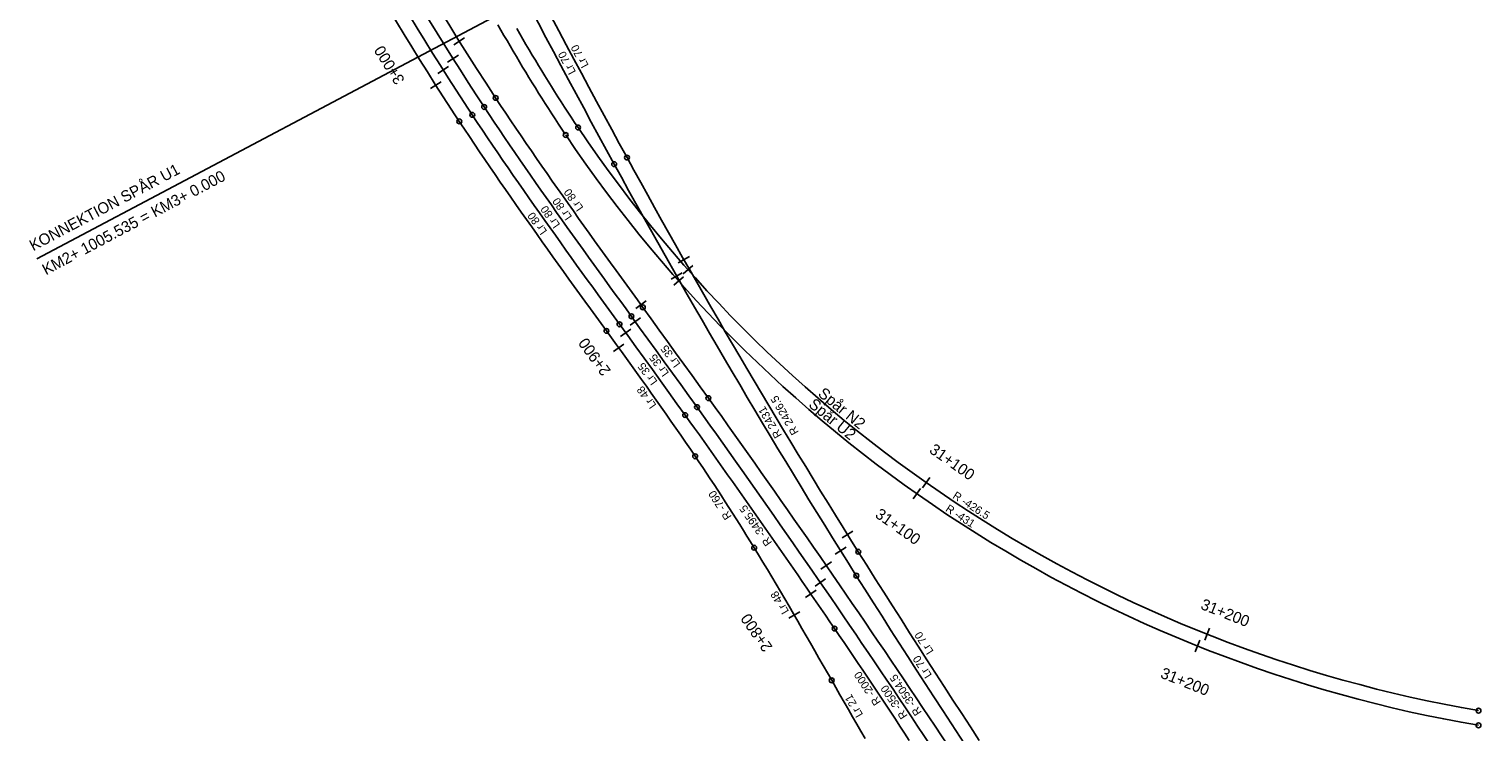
# Model space of a CAD drawing. Extents: x 149855 to 151460, y 6580726 to 6583068.
# Drawn here: x 150980.3 to 151434, y 6581086.8 to 6581306.4 of the extents above; entities that cross this region are included whole.
import ezdxf

# ---------------------------------------------------------------- set-up
doc = ezdxf.new("R2010")
doc.units = 0
for name, color, linetype in [('Hektometer L', 7, 'Continuous'), ('Hektometer T', 7, 'Continuous'), ('Kilometer spm P', 7, 'Continuous'), ('Kilometer spm T', 7, 'Continuous'), ('Konnektion längdmätning L', 7, 'Continuous'), ('Konnektion längdmätning T', 7, 'Continuous'), ('Spår nr T', 7, 'Continuous'), ('Spårgeometri T', 7, 'Continuous'), ('Spårmitt L', 7, 'Continuous'), ('Tp bef behålls P', 7, 'Continuous')]:
    doc.layers.add(name, color=color, linetype=linetype)

msp = doc.modelspace()

# ---------------------------------------------------------------- linework, layer by layer
at = {"layer": 'Hektometer L'}
for points in [[(151113.01, 6581301.55), (151116.4, 6581303.68)], [(151111.05, 6581296.14), (151114.43, 6581298.28)], [(151108.01, 6581292.57), (151111.39, 6581294.72)], [(151105.69, 6581287.83), (151109.07, 6581289.98)], [(151183.16, 6581233.42), (151186.64, 6581235.4)], [(151180.9, 6581228.3), (151184.37, 6581230.28)], [(151169.84, 6581219.13), (151173.08, 6581221.48)], [(151168.07, 6581213.86), (151171.31, 6581216.2)], [(151165.1, 6581210.34), (151168.34, 6581212.69)], [(151162.88, 6581205.67), (151166.12, 6581208.02)], [(151261.74, 6581166.35), (151259.45, 6581163.08)], [(151258.85, 6581162.86), (151256.55, 6581159.59)], [(151234.33, 6581147.42), (151237.73, 6581149.54)], [(151232.19, 6581142.37), (151235.58, 6581144.49)], [(151227.73, 6581137.65), (151231.03, 6581139.93)], [(151225.91, 6581132.34), (151229.2, 6581134.61)], [(151222.9, 6581128.81), (151226.2, 6581131.07)], [(151217.65, 6581122.31), (151221.11, 6581124.32)], [(151346.14, 6581115.5), (151344.65, 6581111.79)], [(151349.13, 6581119.18), (151347.65, 6581115.46)]]:
    msp.add_lwpolyline(points, dxfattribs=at)
at = {"layer": 'Kilometer spm P'}
for p, q in [((151184.79, 6581229.03), (151181.79, 6581226.38)), ((151187.72, 6581232.54), (151184.71, 6581229.9))]:
    msp.add_line(p, q, dxfattribs=at)
at = {"layer": 'Konnektion längdmätning L'}
msp.add_line((150982.75, 6581234.65), (151228.43, 6581364.77), dxfattribs=at)
at = {"layer": 'Spårmitt L'}
for points in [[(151163.13, 6581264.21), (151160.73, 6581268.6), (151158.35, 6581272.99), (151155.96, 6581277.39), (151153.59, 6581281.79), (151151.22, 6581286.19), (151148.86, 6581290.6), (151146.5, 6581295.01), (151144.15, 6581299.42), (151141.8, 6581303.84), (151139.46, 6581308.25), (151137.12, 6581312.67), (151134.78, 6581317.09), (151132.44, 6581321.51), (151130.1, 6581325.93)], [(151167.13, 6581266.28), (151164.73, 6581270.66), (151162.34, 6581275.06), (151159.96, 6581279.45), (151157.59, 6581283.85), (151155.22, 6581288.26), (151152.86, 6581292.66), (151150.5, 6581297.07), (151148.15, 6581301.48), (151145.8, 6581305.9), (151143.45, 6581310.31), (151141.11, 6581314.73), (151138.77, 6581319.15), (151136.43, 6581323.57), (151134.09, 6581327.99)], [(151126.77, 6581307.79), (151127.72, 6581306.13), (151128.68, 6581304.47), (151129.64, 6581302.81), (151130.6, 6581301.16), (151131.57, 6581299.51), (151132.55, 6581297.86), (151133.53, 6581296.21), (151134.51, 6581294.57), (151135.5, 6581292.93), (151136.5, 6581291.3), (151137.5, 6581289.66), (151138.51, 6581288.03), (151139.52, 6581286.41), (151140.54, 6581284.79), (151141.56, 6581283.17), (151142.59, 6581281.56), (151143.63, 6581279.95), (151144.68, 6581278.34), (151145.73, 6581276.74), (151146.78, 6581275.14), (151147.85, 6581273.55)], [(151132.66, 6581306.58), (151133.62, 6581304.92), (151134.59, 6581303.27), (151135.56, 6581301.62), (151136.53, 6581299.97), (151137.51, 6581298.32), (151138.5, 6581296.68), (151139.49, 6581295.04), (151140.48, 6581293.41), (151141.48, 6581291.77), (151142.49, 6581290.15), (151143.5, 6581288.52), (151144.52, 6581286.9), (151145.55, 6581285.28), (151146.58, 6581283.67), (151147.62, 6581282.06), (151148.66, 6581280.46), (151149.71, 6581278.86), (151150.77, 6581277.26), (151151.84, 6581275.67)], [(151172.07, 6581219.47), (151170.39, 6581221.79), (151168.71, 6581224.1), (151167.04, 6581226.41), (151165.36, 6581228.73), (151163.69, 6581231.04), (151162.01, 6581233.36), (151160.34, 6581235.68), (151158.67, 6581237.99), (151157, 6581240.31), (151155.34, 6581242.64), (151153.68, 6581244.96), (151152.02, 6581247.28), (151150.36, 6581249.61), (151148.71, 6581251.94), (151147.06, 6581254.28), (151145.41, 6581256.61), (151143.77, 6581258.95), (151142.13, 6581261.29), (151140.5, 6581263.64), (151138.88, 6581265.99), (151137.25, 6581268.34), (151135.64, 6581270.69), (151134.03, 6581273.06), (151132.42, 6581275.42), (151130.83, 6581277.79), (151129.24, 6581280.16), (151127.65, 6581282.54), (151126.08, 6581284.92)], [(151164.79, 6581214.18), (151163.11, 6581216.49), (151161.43, 6581218.81), (151159.76, 6581221.12), (151158.08, 6581223.43), (151156.41, 6581225.75), (151154.73, 6581228.07), (151153.06, 6581230.38), (151151.39, 6581232.7), (151149.72, 6581235.02), (151148.06, 6581237.34), (151146.4, 6581239.67), (151144.74, 6581241.99), (151143.08, 6581244.32), (151141.42, 6581246.65), (151139.77, 6581248.98), (151138.13, 6581251.32), (151136.49, 6581253.65), (151134.85, 6581256), (151133.22, 6581258.34), (151131.59, 6581260.69), (151129.97, 6581263.04), (151128.35, 6581265.4), (151126.74, 6581267.76), (151125.13, 6581270.12), (151123.53, 6581272.49), (151121.94, 6581274.86), (151120.36, 6581277.24), (151118.78, 6581279.62)], [(151168.51, 6581216.66), (151166.83, 6581218.97), (151165.15, 6581221.29), (151163.48, 6581223.6), (151161.8, 6581225.91), (151160.13, 6581228.23), (151158.45, 6581230.54), (151156.78, 6581232.86), (151155.11, 6581235.18), (151153.44, 6581237.5), (151151.78, 6581239.82), (151150.11, 6581242.14), (151148.45, 6581244.47), (151146.8, 6581246.8), (151145.14, 6581249.13), (151143.49, 6581251.46), (151141.85, 6581253.79), (151140.21, 6581256.13), (151138.57, 6581258.47), (151136.94, 6581260.82), (151135.31, 6581263.17), (151133.69, 6581265.52), (151132.07, 6581267.88), (151130.46, 6581270.23), (151128.85, 6581272.6), (151127.26, 6581274.97), (151125.66, 6581277.34), (151124.08, 6581279.72), (151122.5, 6581282.1)], [(151160.69, 6581212.11), (151159.02, 6581214.42), (151157.34, 6581216.74), (151155.67, 6581219.05), (151153.99, 6581221.37), (151152.32, 6581223.68), (151150.65, 6581226), (151148.98, 6581228.32), (151147.31, 6581230.64), (151145.65, 6581232.96), (151143.98, 6581235.28), (151142.32, 6581237.61), (151140.66, 6581239.93), (151139.01, 6581242.26), (151137.36, 6581244.59), (151135.71, 6581246.93), (151134.06, 6581249.26), (151132.42, 6581251.6), (151130.79, 6581253.95), (151129.16, 6581256.29), (151127.53, 6581258.64), (151125.91, 6581260.99), (151124.29, 6581263.35), (151122.68, 6581265.71), (151121.08, 6581268.08), (151119.48, 6581270.44), (151117.89, 6581272.82), (151116.31, 6581275.2), (151114.73, 6581277.58)], [(151192.56, 6581191.1), (151190.01, 6581194.66), (151187.46, 6581198.21), (151184.9, 6581201.75), (151182.33, 6581205.3), (151179.77, 6581208.85), (151177.2, 6581212.39), (151174.63, 6581215.93), (151172.07, 6581219.47)], [(151189.01, 6581188.29), (151186.45, 6581191.84), (151183.9, 6581195.39), (151181.34, 6581198.94), (151178.78, 6581202.49), (151176.21, 6581206.03), (151173.64, 6581209.58), (151171.08, 6581213.12), (151168.51, 6581216.66)], [(151188.43, 6581172.93), (151186.93, 6581175.14), (151185.42, 6581177.34), (151183.91, 6581179.54), (151182.39, 6581181.73), (151180.87, 6581183.92), (151179.34, 6581186.1), (151177.8, 6581188.28), (151176.26, 6581190.46), (151174.72, 6581192.63), (151173.17, 6581194.8), (151171.62, 6581196.97), (151170.06, 6581199.14), (151168.5, 6581201.3), (151166.94, 6581203.46), (151165.38, 6581205.63), (151163.82, 6581207.79), (151162.26, 6581209.95), (151160.69, 6581212.11)], [(151185.29, 6581185.81), (151182.73, 6581189.36), (151180.18, 6581192.91), (151177.62, 6581196.46), (151175.05, 6581200.01), (151172.49, 6581203.55), (151169.92, 6581207.1), (151167.36, 6581210.64), (151164.79, 6581214.18)], [(151231.08, 6581102.93), (151229.76, 6581105.25), (151228.43, 6581107.56), (151227.11, 6581109.88), (151225.79, 6581112.19), (151224.46, 6581114.51), (151223.13, 6581116.82), (151221.8, 6581119.13), (151220.46, 6581121.44), (151219.13, 6581123.74), (151217.78, 6581126.05), (151216.44, 6581128.35), (151215.08, 6581130.65), (151213.73, 6581132.94), (151212.36, 6581135.24), (151211, 6581137.52), (151209.62, 6581139.81), (151208.24, 6581142.09), (151206.85, 6581144.36)], [(151277.13, 6581084.17), (151274.42, 6581088.37), (151271.7, 6581092.57), (151268.99, 6581096.77), (151266.27, 6581100.97), (151263.56, 6581105.17), (151260.86, 6581109.37), (151258.15, 6581113.58), (151255.45, 6581117.79), (151252.76, 6581122), (151250.07, 6581126.21), (151247.39, 6581130.43), (151244.71, 6581134.66), (151242.04, 6581138.89), (151239.38, 6581143.12)], [(151276.68, 6581076.77), (151273.95, 6581080.96), (151271.22, 6581085.15), (151268.5, 6581089.34), (151265.77, 6581093.54), (151263.05, 6581097.73), (151260.34, 6581101.93), (151257.62, 6581106.13), (151254.91, 6581110.33), (151252.21, 6581114.54), (151249.51, 6581118.74), (151246.82, 6581122.96), (151244.13, 6581127.17), (151241.45, 6581131.4), (151238.78, 6581135.62)], [(151241.52, 6581084.71), (151240.21, 6581086.99), (151238.9, 6581089.26), (151237.59, 6581091.54), (151236.29, 6581093.82), (151234.98, 6581096.09), (151233.68, 6581098.37), (151232.38, 6581100.65), (151231.08, 6581102.93)]]:
    msp.add_lwpolyline(points, dxfattribs=at)
for centre, radius, start, end in [((151877.46, 6581780.33), 900, 202.28355, 213.39793), ((151881.9, 6581783.56), 919, 204.22992, 213.40688), ((151881.9, 6581783.56), 914.5, 204.24219, 213.43976), ((151881.95, 6581783.43), 910, 204.25457, 213.42998), ((151505.71, 6581513.74), 426.5, 213.9318, 260.2137), ((151505.71, 6581513.72), 431, 213.899, 260.3151), ((153295.26, 6582432.02), 2426.5, 208.71299, 212.08503), ((153295.27, 6582432), 2431, 208.70984, 212.22665), ((148345.36, 6579147.78), 3500, 32.03381, 35.662), ((148345.13, 6579148.16), 3504.5, 31.93168, 35.65829), ((148345.19, 6579148.07), 3495.5, 34.32399, 35.65902), ((150559.04, 6580746.94), 760, 31.52858, 34.09137), ((149580.27, 6579991.34), 2000, 33.12146, 34.32399)]:
    msp.add_arc(centre, radius, start, end, dxfattribs=at)
at = {"layer": 'Tp bef behålls P'}
for centre in [(151126.08, 6581284.92), (151118.78, 6581279.62), (151122.5, 6581282.1), (151114.73, 6581277.58), (151147.97, 6581273.34), (151151.84, 6581275.67), (151163.13, 6581264.21), (151167.13, 6581266.27), (151172.07, 6581219.47), (151164.79, 6581214.18), (151168.51, 6581216.66), (151160.69, 6581212.11), (151189.01, 6581188.29), (151192.56, 6581191.1), (151185.29, 6581185.81), (151188.43, 6581172.93), (151206.85, 6581144.36), (151239.39, 6581143.11), (151238.78, 6581135.62), (151231.99, 6581119.09), (151231.08, 6581102.93), (151433.21, 6581093.45), (151433.2, 6581088.86)]:
    msp.add_circle(centre, 0.75, dxfattribs=at)

# ---------------------------------------------------------------- texts
at = {"layer": 'Hektometer T'}
for s, rotation, p in [('2+900', 125.9475, (151162.24, 6581199.69)), ('31+100', 324.921, (151261.31, 6581174.28)), ('31+100', 324.8698, (151244.36, 6581154.1)), ('31+200', 338.3549, (151346.11, 6581125.32)), ('2+800', 124.565, (151212.75, 6581113.36)), ('31+200', 338.1635, (151333.56, 6581103.84))]:
    msp.add_text(s, height=3.5, rotation=rotation, dxfattribs=at).set_placement(p)
at = {"layer": 'Kilometer spm T'}
msp.add_text('3+000', height=3.5, rotation=121.949, dxfattribs=at).set_placement((151097.82, 6581290.51))
at = {"layer": 'Konnektion längdmätning T'}
for s, p in [('KONNEKTION SPÅR U1', (150981.58, 6581236.98)), ('KM2+ 1005.535 = KM3+ 0.000', (150985.56, 6581229.47))]:
    msp.add_text(s, height=3.5, rotation=27.9146, dxfattribs=at).set_placement(p)
at = {"layer": 'Spår nr T'}
for s, rotation, p in [('Spår N2', 320.6288, (151226.54, 6581192.04)), ('Spår U2', 320.5244, (151223.6, 6581188.67))]:
    msp.add_text(s, height=3.5, rotation=rotation, dxfattribs=at).set_placement(p)
at = {"layer": 'Spårgeometri T'}
for s, rotation, p in [('Lr 70', 118.162, (151155.23, 6581295.13)), ('Lr 70', 118.1599, (151151.23, 6581293.06)), ('Lr 80', 125.0956, (151153.62, 6581250.61)), ('Lr 80', 125.109, (151150.06, 6581247.79)), ('Lr 80', 125.0694, (151142.27, 6581243.25)), ('Lr 80', 125.1105, (151146.34, 6581245.31)), ('Lr 35', 125.849, (151183.94, 6581201.8)), ('Lr 35', 125.8503, (151176.77, 6581196.29)), ('Lr 35', 125.853, (151180.38, 6581198.99)), ('Lr 48', 125.2976, (151176.42, 6581188.92)), ('R 2431', 120.4682, (151215.61, 6581179.49)), ('R 2426.5', 120.399, (151220.87, 6581180.48)), ('R -760', 122.81, (151199.92, 6581154.08)), ('R -426.5', 327.0723, (151268.67, 6581160.02)), ('R -3495.5', 124.9915, (151212.55, 6581145.96)), ('R -431', 327.1084, (151266.43, 6581155.95)), ('Lr 48', 120.3224, (151217.82, 6581124.51)), ('Lr 70', 122.636, (151263.02, 6581112.01)), ('Lr 70', 122.7766, (151262.49, 6581104.57)), ('R -2000', 123.7227, (151246.56, 6581096.1)), ('R -3504.5', 123.795, (151259.3, 6581092.91)), ('Lr 21', 119.8271, (151240.96, 6581092.21)), ('R -3500', 123.8479, (151254.89, 6581091.85))]:
    msp.add_text(s, height=2.5, rotation=rotation, dxfattribs=at).set_placement(p)

doc.saveas('drawing.dxf')
